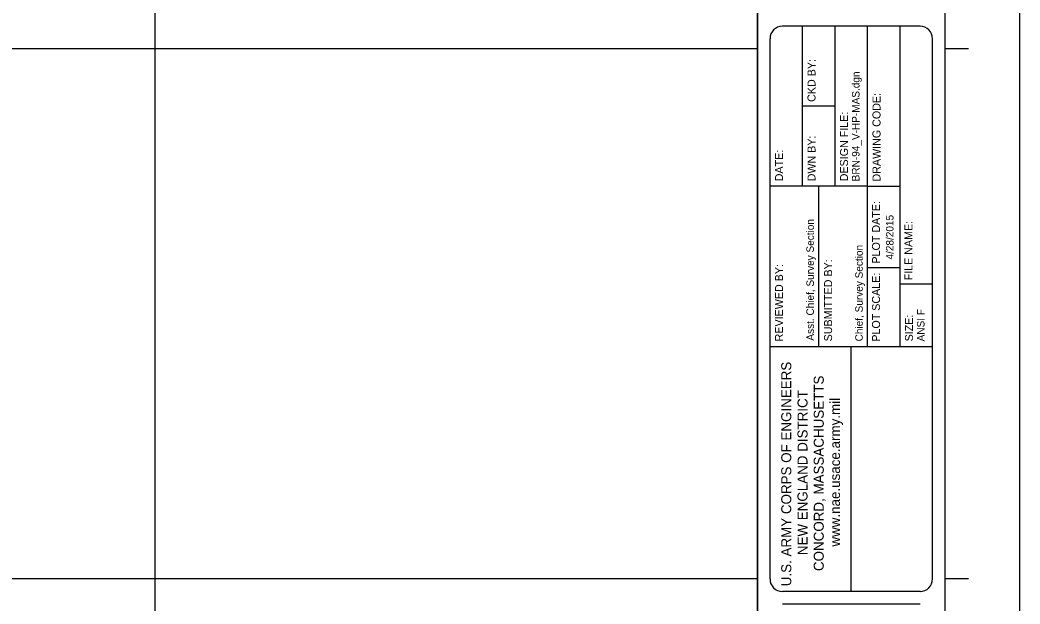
# Model space of a CAD drawing. Extents: x 0 to 3.33, y 0 to 2.33.
# Drawn here: x 2.5 to 3.333, y 0.483 to 0.97 of the extents above; entities that cross this region are included whole.
import ezdxf

# ---------------------------------------------------------------- set-up
doc = ezdxf.new("R2010")
doc.units = 0
for name, color, linetype in [('G-ANNO-NPLT', 7, 'Continuous'), ('G-ANNO-TEXT', 7, 'Continuous'), ('G-ANNO-TTLB', 7, 'Continuous'), ('G-ANNO-TTLB-GRID', 7, 'Continuous')]:
    doc.layers.add(name, color=color, linetype=linetype)

msp = doc.modelspace()

# ---------------------------------------------------------------- linework, layer by layer
at = {"layer": 'G-ANNO-NPLT'}
msp.add_lwpolyline([(0, 0), (3.33333, 0), (3.33333, 2.33333), (0, 2.33333)], close=True, dxfattribs=at)
at = {"layer": 'G-ANNO-TTLB'}
for p, q in [((3.15209, 0.83125), (3.15209, 0.96459)), ((3.17917, 0.83125), (3.17917, 0.96459)), ((3.20626, 0.69792), (3.20626, 0.96459)), ((3.23334, 0.69792), (3.23334, 0.96459)), ((3.12501, 0.50417), (3.12501, 0.95417)), ((3.29053, 0.94584), (3.27084, 0.94584)), ((3.17917, 0.89792), (3.15209, 0.89792)), ((3.15221, 0.83125), (3.12501, 0.83125)), ((3.17929, 0.83125), (3.15209, 0.83125)), ((3.16563, 0.69792), (3.16563, 0.83125)), ((3.20626, 0.83125), (3.17917, 0.83125)), ((3.23334, 0.83123), (3.20626, 0.83123)), ((3.23331, 0.76326), (3.20626, 0.76326)), ((3.26042, 0.74985), (3.23334, 0.74985)), ((3.12501, 0.69792), (3.26042, 0.69792)), ((3.19271, 0.49375), (3.19271, 0.69792)), ((3.29053, 0.50417), (3.27084, 0.50417))]:
    msp.add_line(p, q, dxfattribs=at)
for points in [[(0.12501, 0.0625), (3.11459, 0.0625), (3.11459, 2.27084), (0.12501, 2.27084)], [(3.11459, 0.0625), (3.27084, 0.0625), (3.27084, 2.27084), (3.11459, 2.27084)]]:
    msp.add_lwpolyline(points, close=True, dxfattribs=at)
for points in [[(3.25001, 0.96459), (3.13542, 0.96459)], [(3.25001, 0.96459), (3.13542, 0.96459)], [(3.25001, 0.96459), (3.13542, 0.96459)], [(3.26042, 0.50417), (3.26042, 0.95417)], [(3.25001, 0.49375), (3.13542, 0.49375)], [(3.13542, 0.48334), (3.25001, 0.48334)]]:
    msp.add_lwpolyline(points, dxfattribs=at)
for centre, start, end in [((3.13542, 0.95417), 90, 180), ((3.13542, 0.95417), 90, 180), ((3.13542, 0.95417), 90, 180), ((3.25001, 0.95417), 0, 90), ((3.25001, 0.95417), 0, 90), ((3.25001, 0.95417), 0, 90), ((3.13542, 0.50417), 180, 270), ((3.25001, 0.50417), 270, 0)]:
    msp.add_arc(centre, 0.01042, start, end, dxfattribs=at)
at = {"layer": 'G-ANNO-TTLB-GRID'}
for p, q in [((2.61251, 0.0625), (2.61251, 2.27084)), ((3.11459, 0.94584), (0.12501, 0.94584)), ((3.11459, 0.50417), (0.12501, 0.50417))]:
    msp.add_line(p, q, dxfattribs=at)

# ---------------------------------------------------------------- texts
at = {"layer": 'G-ANNO-TEXT'}
for s, height, p in [('CKD BY:', 0.006667, (3.16292, 0.90159)), ('BRN-94_V-HP-MAS.dgn', 0.00625, (3.19959, 0.83542)), ('DRAWING CODE:', 0.0066667, (3.21709, 0.83525)), ('DESIGN FILE:', 0.0066667, (3.19001, 0.83542)), ('DWN BY:', 0.006667, (3.16292, 0.83542)), ('DATE:', 0.006667, (3.13585, 0.83542)), ('PLOT DATE:', 0.006667, (3.21668, 0.76692)), ('Asst. Chief, Survey Section', 0.00625, (3.16157, 0.70271)), ('FILE NAME:', 0.006667, (3.24372, 0.75294)), ('Chief, Survey Section', 0.00625, (3.2023, 0.70209)), ('SUBMITTED BY:', 0.0066667, (3.17673, 0.70209)), ('REVIEWED BY:', 0.0066667, (3.13585, 0.70209)), ('PLOT SCALE:', 0.0066667, (3.21668, 0.70185)), ('SIZE:', 0.006667, (3.24417, 0.70209))]:
    msp.add_text(s, height=height, rotation=90, dxfattribs=at).set_placement(p)
at = {"layer": 'G-ANNO-TTLB'}
for s, height, p in [(' 4/28/2015', 0.00625, (3.22791, 0.76796)), ('ANSI F', 0.00625, (3.25376, 0.70209)), ('U.S. ARMY CORPS OF ENGINEERS', 0.0083333, (3.14271, 0.49814)), ('CONCORD, MASSACHUSETTS', 0.0083333, (3.1698, 0.51076)), ('NEW ENGLAND DISTRICT', 0.0083333, (3.15626, 0.52403)), ('www.nae.usace.army.mil', 0.0083333, (3.18334, 0.53115))]:
    msp.add_text(s, height=height, rotation=90, dxfattribs=at).set_placement(p)

doc.saveas('drawing.dxf')
